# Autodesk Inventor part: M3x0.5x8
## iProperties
Created: 2009-02
Part Number: M3x0.5x8
Material: 강, 연강
Description: 6각 너트 및 6각 가는 너트
Document SubType Name: Modeling
Standard: KS B 1012
Designer: KYOUNG IL JANG
Standards Organization: KS
Language: ko-KR
Size Designation: C M8
Categories: <MemberInstance><Categories><Category DisplayName="조임쇠" InternalName="e4da775c-781d-43d5-af7c-5136215cf5a6" Mnemonic="FSTN"><Category DisplayName="너트" InternalN
Density: 1 g/cm^3
Vendor: CBT Solutions
Company: 한국ATC센터
IsCustomPart: 0
Author: KYOUNG IL JANG
